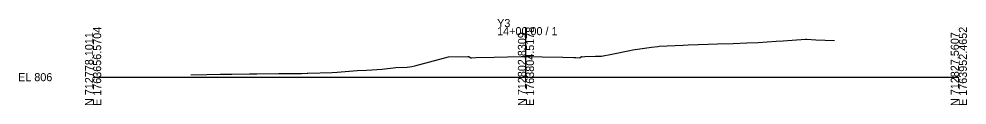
# Model space of a CAD drawing. Extents: x -26 to 2903, y -10 to 5022.
# Drawn here: x -25.7 to 302.8, y 3990.3 to 4020.2 of the extents above; entities that cross this region are included whole.
import ezdxf

# ---------------------------------------------------------------- set-up
doc = ezdxf.new("R2010")
doc.units = 0
for name, color, linetype in [('Default', 7, 'Continuous'), ('Exist Cross Section Cell', 7, 'Continuous'), ('Exist XS Ground Line', 7, 'Continuous')]:
    doc.layers.add(name, color=color, linetype=linetype)

msp = doc.modelspace()

# ---------------------------------------------------------------- linework, layer by layer
at = {"layer": 'Exist Cross Section Cell'}
for p, q in [((150, 4000), (150, 4017.37)), ((0, 4000), (150, 4000)), ((150, 4000), (300, 4000))]:
    msp.add_line(p, q, dxfattribs=at)
at = {"layer": 'Exist XS Ground Line'}
msp.add_lwpolyline([(33.89, 4000.79), (39.38, 4000.92), (44.03, 4001.01), (48.06, 4001.07), (54.17, 4001.14), (56.75, 4001.13), (64.31, 4001.23), (65.44, 4001.26), (72.17, 4001.31), (74.12, 4001.33), (74.45, 4001.34), (82.81, 4001.66), (84.59, 4001.74), (91.5, 4002.26), (94.73, 4002.43), (100.18, 4002.82), (104.86, 4003.4), (108.78, 4003.52), (110.46, 4003.67), (111.52, 4003.94), (123.17, 4007), (129.88, 4007.2), (130.16, 4007.21), (130.7, 4006.84), (130.84, 4006.71), (131.27, 4006.76), (132.64, 4006.85), (138.98, 4006.97), (143.65, 4007.04), (148.28, 4007.14), (149.58, 4007.17), (150, 4007.16), (151.46, 4007.14), (155.65, 4007.08), (162.82, 4006.91), (166.61, 4006.84), (167.31, 4006.77), (168.55, 4006.68), (168.8, 4006.87), (169.29, 4007.18), (169.72, 4007.11), (170.37, 4007.12), (174.13, 4007.23), (176.19, 4007.26), (179.73, 4007.95), (185.97, 4009.24), (187.05, 4009.46), (193.48, 4010.36), (195.74, 4010.67), (196.11, 4010.73), (204.42, 4011.08), (206.25, 4011.2), (213.11, 4011.44), (216.39, 4011.57), (221.8, 4011.7), (226.53, 4011.9), (230.48, 4012.06), (236.67, 4012.49), (239.17, 4012.66), (246.81, 4013.14), (247.37, 4013.18), (250.4, 4012.98), (256.95, 4012.72)], dxfattribs=at)

# ---------------------------------------------------------------- texts
at = {"layer": 'Default'}
msp.add_text('-', height=0.0001, dxfattribs=at).set_placement((0, 4000))
at = {"layer": 'Exist Cross Section Cell'}
for s, p in [('Y3', (140, 4017.37)), ('14+00.00 / 1', (140, 4014.57)), ('EL 806', (-26, 3998.6))]:
    msp.add_text(s, height=2.8, dxfattribs=at).set_placement(p)
for s, p in [('N 712778.1011', (0, 3990)), ('E 1763656.5704', (2.8, 3990)), ('N 712802.8309', (150, 3990)), ('E 1763804.5178', (152.8, 3990)), ('N 712827.5607', (300, 3990)), ('E 1763952.4652', (302.8, 3990))]:
    msp.add_text(s, height=2.8, rotation=90, dxfattribs=at).set_placement(p)

doc.saveas('drawing.dxf')
